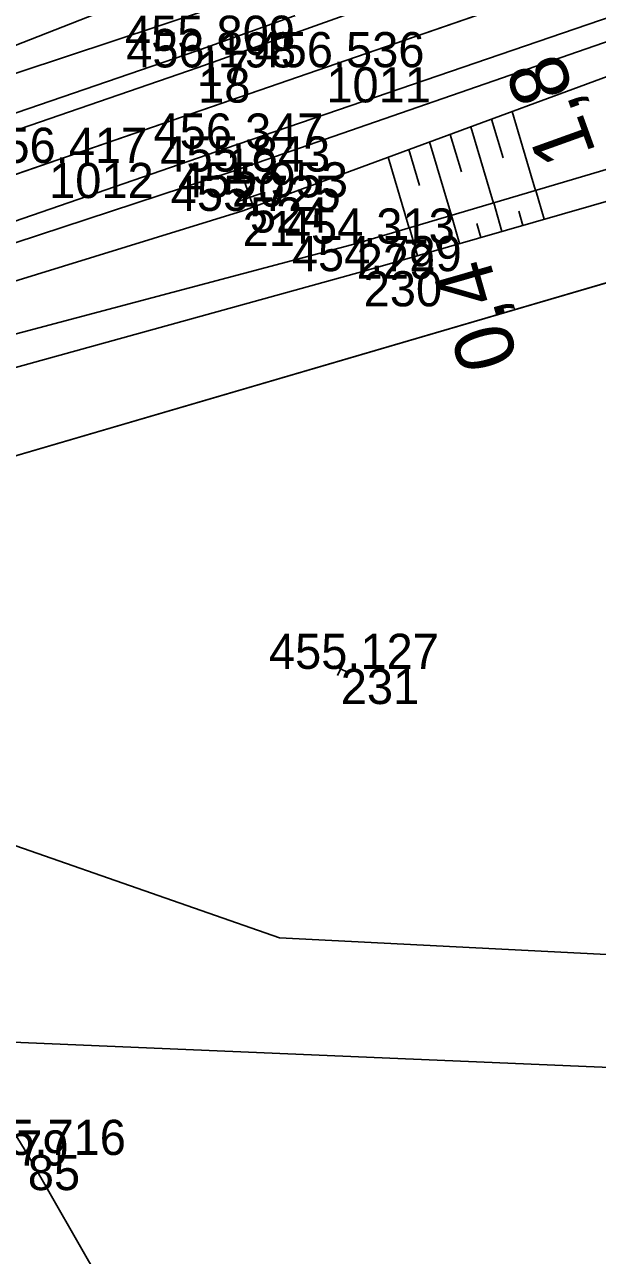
# Model space of a CAD drawing. Extents: x -776734 to -748832, y -1118122 to -976986.
# Drawn here: x -750886.83 to -750867.27, y -1114636.27 to -1114594.26 of the extents above; entities that cross this region are included whole.
import ezdxf

# ---------------------------------------------------------------- set-up
doc = ezdxf.new("R2010")
doc.units = 0
for name, color, linetype in [('KM_Hranice parcel', 7, 'Continuous'), ('Obvod stavby - SŽ+ČD', 7, 'Continuous'), ('OSA', 7, 'Continuous'), ('SŽG Vrstva 1', 7, 'Continuous'), ('SŽG Vrstva 4', 7, 'Continuous'), ('SŽG Vrstva 48', 7, 'Continuous'), ('SŽG Vrstva 49', 7, 'Continuous'), ('SŽG Vrstva 53', 7, 'Continuous'), ('SŽG Vrstva 60', 7, 'Continuous'), ('SŽG Vrstva 61', 7, 'Continuous'), ('SŽG Vrstva 7', 7, 'Continuous')]:
    doc.layers.add(name, color=color, linetype=linetype)

msp = doc.modelspace()

# ---------------------------------------------------------------- linework, layer by layer
at = {"layer": 'KM_Hranice parcel'}
for points in [[(-750611.11, -1114513.75), (-750618.96, -1114520.66), (-750640.98, -1114532.02), (-750662.65, -1114539.99), (-750681.82, -1114546.44), (-750707.75, -1114555.36), (-750804.97, -1114584.92), (-750894.76, -1114611.21), (-750899.97, -1114614.15)], [(-750898.99, -1114623.24), (-750890.19, -1114628.86), (-750790.97, -1114633.08), (-750787.69, -1114636.32), (-750785.63, -1114639.42), (-750784.78, -1114643.94), (-750782.09, -1114625.64), (-750786.55, -1114630.1), (-750878.13, -1114625.43), (-750891.51, -1114620.76), (-750899.97, -1114614.15)]]:
    msp.add_lwpolyline(points, dxfattribs=at)
at = {"layer": 'Obvod stavby - SŽ+ČD'}
msp.add_lwpolyline([(-751001.9301, -1114630.5149), (-750919.7259, -1114602.1536), (-750923.65, -1114590.78), (-750909.46, -1114590.94), (-750904.52, -1114591.74), (-750900.07, -1114579.45), (-750884.93, -1114572.87), (-750860.41, -1114581.47), (-750855.8233, -1114579.7245), (-750849.5295, -1114597.9668), (-750894.76, -1114611.21), (-750899.97, -1114614.15), (-750906.35, -1114617.75), (-750913.4946, -1114620.2148), (-750914.5076, -1114617.2787), (-750996.7117, -1114645.64)], dxfattribs=at)
at = {"layer": 'OSA'}
msp.add_line((-750860.923, -1114590.3276), (-750912.9148, -1114608.268), dxfattribs=at)
at = {"layer": 'SŽG Vrstva 1'}
msp.add_lwpolyline([(-750820.337, -1114576.326), (-750829.58, -1114579.518), (-750838.838, -1114582.712), (-750848.38, -1114586.005), (-750858.075, -1114589.346), (-750867.336, -1114592.541), (-750876.526, -1114595.715), (-750885.989, -1114598.98), (-750895.385, -1114602.229), (-750902.991, -1114604.843), (-750908.211, -1114606.647), (-750914.742, -1114608.898), (-750924.077, -1114612.114), (-750933.495, -1114615.368), (-750942.896, -1114618.61), (-750952.239, -1114621.829), (-750961.799, -1114625.127)], dxfattribs=at)
at = {"layer": 'SŽG Vrstva 4'}
for points in [[(-750824.673, -1114575.386), (-750842.852, -1114581.727), (-750861.561, -1114588.189), (-750880.945, -1114595.155), (-750899.361, -1114601.468), (-750902.908, -1114603.401)], [(-750824.563, -1114575.932), (-750842.715, -1114582.202), (-750861.411, -1114588.769), (-750880.904, -1114595.722), (-750899.175, -1114602.016), (-750902.908, -1114603.401)], [(-750823.32, -1114578.973), (-750841.487, -1114585.259), (-750860.348, -1114591.764), (-750879.972, -1114598.494), (-750898.231, -1114604.794), (-750901.922, -1114606.212)], [(-750823.034, -1114579.626), (-750841.271, -1114586.102), (-750860.173, -1114592.481), (-750879.743, -1114599.276), (-750897.921, -1114605.245), (-750901.922, -1114606.212)]]:
    msp.add_lwpolyline(points, dxfattribs=at)
at = {"layer": 'SŽG Vrstva 48'}
for p, q in [((-750870.1822, -1114597.2249), (-750869.382, -1114599.9223)), ((-750871.5925, -1114597.7451), (-750870.82, -1114600.349)), ((-750870.8874, -1114597.485), (-750870.4942, -1114598.8103)), ((-750873.0028, -1114598.2652), (-750872.2581, -1114600.7756)), ((-750872.2977, -1114598.0052), (-750871.9184, -1114599.2837)), ((-750873.708, -1114598.5253), (-750873.3426, -1114599.7571)), ((-750874.4131, -1114598.7854), (-750873.6961, -1114601.2022)), ((-750869.094, -1114600.905), (-750869.377, -1114599.921)), ((-750870.536, -1114601.319), (-750870.815, -1114600.348)), ((-750871.977, -1114601.734), (-750872.253, -1114600.774)), ((-750869.815, -1114601.112), (-750869.956, -1114600.623)), ((-750873.419, -1114602.149), (-750873.692, -1114601.201)), ((-750871.257, -1114601.527), (-750871.395, -1114601.044)), ((-750872.698, -1114601.941), (-750872.835, -1114601.464))]:
    msp.add_line(p, q, dxfattribs=at)
at = {"layer": 'SŽG Vrstva 49'}
for p, q in [((-750875.8093, -1114616.3595), (-750876.2587, -1114616.1405)), ((-750875.9245, -1114616.0253), (-750876.1435, -1114616.4747)), ((-750886.717, -1114632.841), (-750896.148, -1114617.498)), ((-750886.717, -1114632.841), (-750879.898, -1114644.696))]:
    msp.add_line(p, q, dxfattribs=at)
for points in [[(-750902.869, -1114601.131), (-750876.43, -1114590.758), (-750847.082, -1114577.508), (-750846.11, -1114576.392), (-750828.341, -1114569.281)], [(-750829.333, -1114576.055), (-750875.877, -1114592.182), (-750902.869, -1114601.131)], [(-750823, -1114580.577), (-750841.163, -1114586.823), (-750860.183, -1114593.537), (-750879.382, -1114600.618), (-750897.603, -1114606.242), (-750900.708, -1114608.016), (-750901.423, -1114610.555), (-750897.925, -1114617.962)], [(-750826.229, -1114587.12), (-750875.492, -1114601.735), (-750898.314, -1114607.786)], [(-750825.879, -1114588.474), (-750875.252, -1114602.676), (-750897.922, -1114608.949)]]:
    msp.add_lwpolyline(points, dxfattribs=at)
at = {"layer": 'SŽG Vrstva 53'}
msp.add_lwpolyline([(-750804.97, -1114584.92), (-750894.76, -1114611.21), (-750899.97, -1114614.15), (-750906.35, -1114617.75), (-750903.28, -1114626.63), (-750977.55, -1114652.09), (-751017.8, -1114665.47), (-751047.63, -1114693.52)], dxfattribs=at)
at = {"layer": 'SŽG Vrstva 60'}
for p, q in [((-750880.945, -1114595.155), (-750880.945, -1114595.155)), ((-750880.904, -1114595.722), (-750880.904, -1114595.722)), ((-750876.526, -1114595.715), (-750876.526, -1114595.715)), ((-750879.972, -1114598.494), (-750879.972, -1114598.494)), ((-750885.989, -1114598.98), (-750885.989, -1114598.98)), ((-750879.743, -1114599.276), (-750879.743, -1114599.276)), ((-750879.136, -1114600.158), (-750879.136, -1114600.158)), ((-750879.382, -1114600.618), (-750879.382, -1114600.618)), ((-750875.492, -1114601.735), (-750875.492, -1114601.735)), ((-750875.252, -1114602.676), (-750875.252, -1114602.676)), ((-750876.034, -1114616.25), (-750876.034, -1114616.25)), ((-750886.717, -1114632.841), (-750886.717, -1114632.841))]:
    msp.add_line(p, q, dxfattribs=at)
at = {"layer": 'SŽG Vrstva 7'}
for p, q in [((-750878.9729, -1114600.6307), (-750879.2991, -1114599.6853)), ((-750878.6633, -1114599.9949), (-750879.6087, -1114600.3211))]:
    msp.add_line(p, q, dxfattribs=at)

# ---------------------------------------------------------------- texts
at = {"layer": 'SŽG Vrstva 48'}
for s, rotation, p in [('1,8', 109.7737, (-750867.307, -1114598.631)), ('0,4', 106.04773, (-750869.963, -1114605.732))]:
    msp.add_text(s, height=2, rotation=rotation, dxfattribs=at).set_placement(p)
at = {"layer": 'SŽG Vrstva 60'}
for s, p in [('17', (-750880.945, -1114596.355)), ('18', (-750880.904, -1114596.922)), ('1011', (-750876.526, -1114596.915)), ('19', (-750879.972, -1114599.694)), ('1012', (-750885.989, -1114600.18)), ('20', (-750879.743, -1114600.476)), ('524', (-750879.136, -1114601.358)), ('21', (-750879.382, -1114601.818)), ('229', (-750875.492, -1114602.935)), ('230', (-750875.252, -1114603.876)), ('231', (-750876.034, -1114617.45)), ('85', (-750886.717, -1114634.041))]:
    msp.add_text(s, height=1.2, dxfattribs=at).set_placement(p)
at = {"layer": 'SŽG Vrstva 61'}
for s, p in [('455.809', (-750883.3987, -1114595.155)), ('456.198', (-750883.3577, -1114595.722)), ('456.536', (-750878.9779, -1114595.715)), ('456.347', (-750882.4239, -1114598.494)), ('456.417', (-750888.4409, -1114598.98)), ('455.843', (-750882.1949, -1114599.276)), ('455.953', (-750881.5879, -1114600.158)), ('455.725', (-750881.8381, -1114600.618)), ('454.313', (-750877.9439, -1114601.735)), ('454.729', (-750877.7057, -1114602.676)), ('455.127', (-750878.4859, -1114616.25)), ('455.716', (-750889.1689, -1114632.841)), ('456.379', (-750891.1257, -1114633.201))]:
    msp.add_text(s, height=1.2, dxfattribs=at).set_placement(p)

doc.saveas('drawing.dxf')
